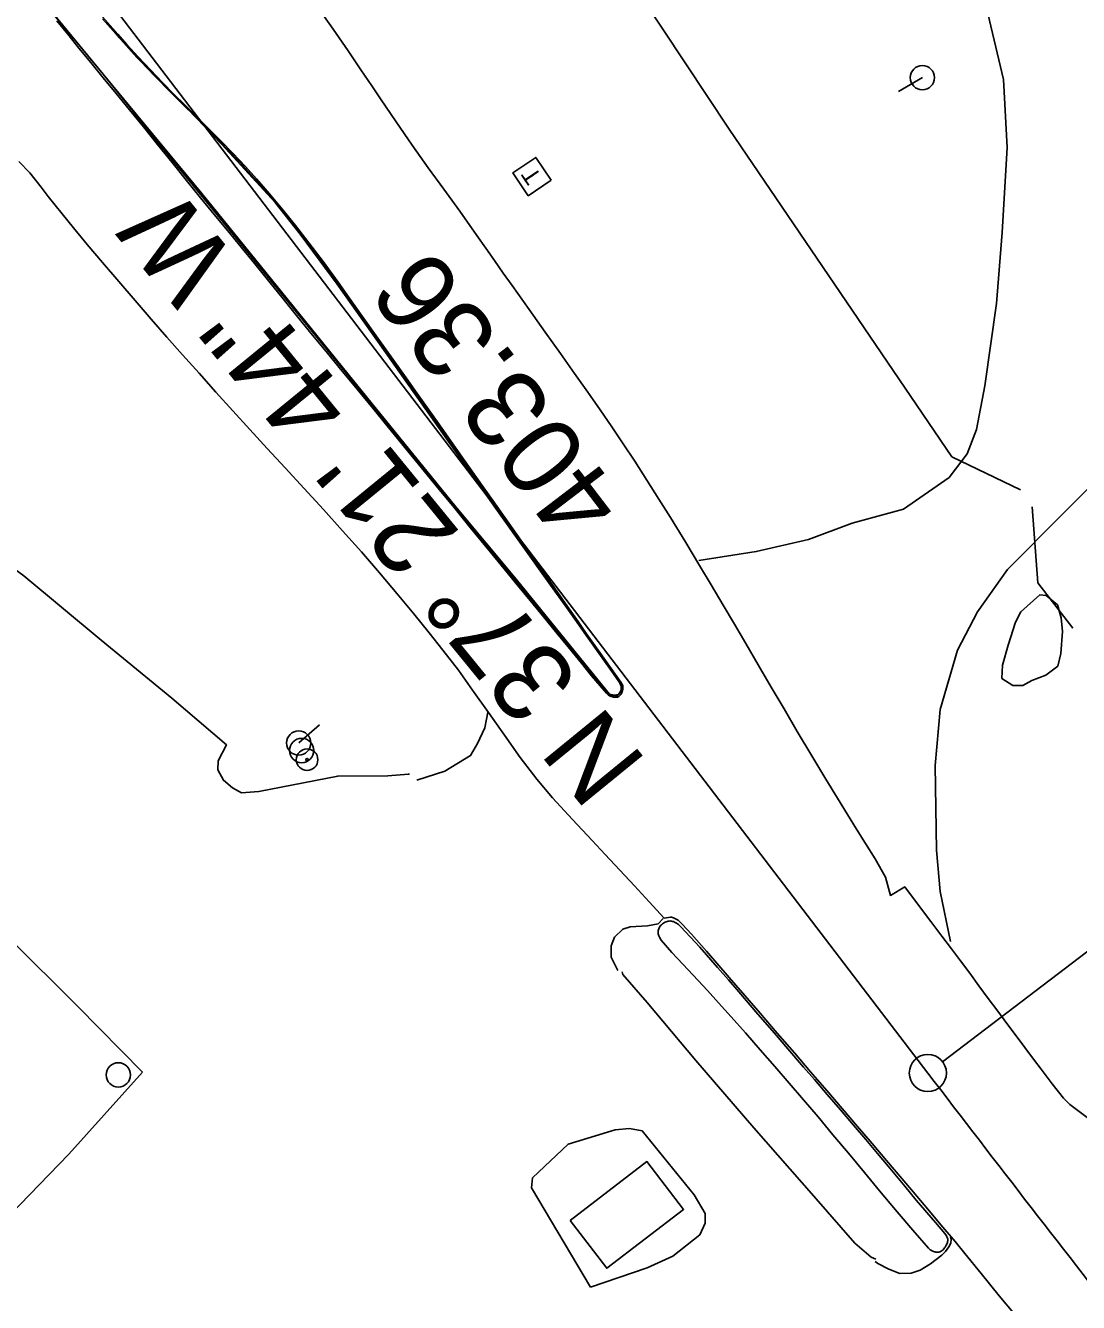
# Model space of a CAD drawing. Extents: x 471894 to 476235, y 503501 to 507878.
# Drawn here: x 473726.4 to 473939.4, y 505870.1 to 506128.6 of the extents above; entities that cross this region are included whole.
import ezdxf

# ---------------------------------------------------------------- set-up
doc = ezdxf.new("R2010")
doc.units = 0
for name, color, linetype in [('Exist Horizontal Alignment', 7, 'Continuous'), ('Exist Horizontal Alignment Direction Label', 7, 'Continuous'), ('Exist Other Culture Area Outline', 7, 'Continuous'), ('Exist Other Culture Fence Line', 7, 'Continuous'), ('Exist Other Culture Gate', 7, 'Continuous'), ('Exist Roads Curbs', 7, 'Continuous'), ('Exist Roads EOP', 7, 'Continuous'), ('Exist Roads EOP Other', 7, 'Continuous'), ('Exist Roads Soil', 7, 'Continuous'), ('Exist Utilities Other Located Object CELL', 7, 'Continuous'), ('Exist Utilities Other Pole CELL', 7, 'Continuous'), ('Exist Utilities Power Pole CELL', 7, 'Continuous'), ('Exist Utilities Telephone Pedestal CELL', 7, 'Continuous')]:
    doc.layers.add(name, color=color, linetype=linetype)

msp = doc.modelspace()

# ---------------------------------------------------------------- linework, layer by layer
at = {"layer": 'Exist Horizontal Alignment'}
for p, q in [((473908.93, 505916.58), (473664.15, 506237.18)), ((473911.91, 505918.85), (473979.21, 505970.23))]:
    msp.add_line(p, q, dxfattribs=at)
msp.add_circle((473908.93, 505916.58), 3.75, dxfattribs=at)
msp.add_arc((478558.54, 509466.62), 5849.93, 217.36226, 218.70549, dxfattribs=at)
at = {"layer": 'Exist Other Culture Area Outline'}
msp.add_lwpolyline([(473932.83, 506013.22), (473935.18, 506011.29), (473935.91, 506008.66), (473936.14, 506005.96), (473935.8, 506001.47), (473935.23, 505998.93), (473932.8, 505997.07), (473929.94, 505995.99), (473928.15, 505995.03), (473926.14, 505994.97), (473923.9, 505996.42), (473924.01, 505999.13), (473925.14, 506003.16), (473926.63, 506007.82), (473927.73, 506009.9), (473931.57, 506013.33), (473932.83, 506013.22)], dxfattribs=at)
msp.add_lwpolyline([(473836.55, 505886.76), (473852.1, 505898.67), (473859.52, 505888.98), (473843.98, 505877.07)], close=True, dxfattribs=at)
at = {"layer": 'Exist Other Culture Fence Line'}
msp.add_line((473938.23, 506006.61), (473931.19, 506015.78), dxfattribs=at)
msp.add_lwpolyline([(473913.78, 506041.26), (473868.72, 506107.56), (473819.7, 506181.61), (473863.62, 506226.96), (473925.15, 506291.5), (473965.74, 506322.98)], dxfattribs=at)
at = {"layer": 'Exist Other Culture Gate'}
for p, q in [((473927.69, 506034.58), (473913.78, 506041.26)), ((473931.19, 506015.78), (473930.02, 506031.17))]:
    msp.add_line(p, q, dxfattribs=at)
at = {"layer": 'Exist Roads Curbs'}
for points in [[(473729.8, 506133.75), (473747.2, 506112.55), (473762.04, 506094.58), (473779.35, 506073.27), (473791.58, 506058.07), (473813.37, 506031.23), (473825.63, 506016.54), (473837.49, 506001.85), (473844.51, 505993.27), (473845.56, 505993.02), (473846.36, 505993.17), (473846.82, 505993.81), (473846.92, 505994.37), (473846.89, 505994.89), (473846.65, 505995.44), (473846.47, 505995.98), (473832.29, 506015.75), (473821.57, 506030.85), (473810.83, 506045.98), (473797.68, 506064.6), (473789.47, 506076.22), (473781.98, 506086.36), (473776.89, 506092.71), (473766.1, 506104.47), (473757.5, 506113.42), (473748.94, 506122.09), (473741.98, 506129.92)], [(473731.9, 506131.08), (473742.1, 506118.69), (473753.47, 506104.63), (473767.01, 506088.03), (473778.28, 506074.2), (473790.38, 506059.26), (473804.31, 506042.24), (473817.69, 506025.78), (473833.87, 506005.97), (473842.71, 505995.12), (473844.02, 505993.55), (473844.49, 505993.19), (473844.75, 505993.04), (473845.13, 505992.95), (473845.54, 505992.9), (473845.93, 505992.93), (473846.26, 505993.13), (473846.52, 505993.37), (473846.65, 505993.59), (473846.79, 505993.85), (473846.87, 505994.08), (473846.91, 505994.35), (473846.92, 505994.6), (473846.91, 505994.86), (473846.7, 505995.43), (473846.3, 505996.03), (473844.17, 505999.01), (473840.22, 506004.61), (473832.1, 506016.1), (473826.41, 506024.14), (473818.83, 506034.91), (473810.76, 506046.32), (473804, 506055.98), (473797.9, 506064.54), (473790.82, 506074.63), (473788.67, 506077.63), (473786.81, 506080.13), (473784.08, 506083.78), (473782.07, 506086.35), (473779.85, 506089.26), (473777.62, 506091.92), (473775.42, 506094.52), (473773.65, 506096.53), (473771.95, 506098.47), (473769.74, 506100.89), (473767.48, 506103.28), (473764.28, 506106.6), (473760.94, 506109.91), (473758.03, 506112.78), (473755.47, 506115.31), (473752.82, 506118.01), (473750.81, 506120.14), (473748.4, 506122.79), (473745.45, 506126.08), (473742.7, 506129.22)]]:
    msp.add_lwpolyline(points, dxfattribs=at)
msp.add_lwpolyline([(473902.72, 505888.5), (473905.88, 505884.75), (473909.07, 505881.14), (473909.41, 505880.82), (473910.07, 505880.48), (473910.24, 505880.41), (473910.41, 505880.36), (473910.56, 505880.32), (473910.71, 505880.3), (473910.86, 505880.3), (473911.01, 505880.3), (473911.16, 505880.33), (473911.32, 505880.37), (473911.48, 505880.43), (473911.65, 505880.53), (473911.82, 505880.65), (473912, 505880.81), (473912.32, 505881.17), (473912.45, 505881.35), (473912.66, 505881.73), (473912.82, 505882.1), (473912.88, 505882.29), (473912.92, 505882.47), (473912.95, 505882.64), (473912.95, 505882.79), (473912.94, 505882.93), (473912.88, 505883.19), (473912.79, 505883.46), (473912.71, 505883.63), (473912.37, 505884.11), (473910.5, 505886.33), (473906.58, 505890.88), (473904.3, 505893.65), (473900.92, 505897.72), (473898.75, 505900.31), (473896.38, 505903.13), (473893.89, 505906.06), (473891.28, 505909.11), (473888.56, 505912.26), (473885.99, 505915.25), (473883.8, 505917.78), (473880.62, 505921.47), (473877.91, 505924.62), (473874.57, 505928.51), (473870.7, 505933), (473868.6, 505935.42), (473866.4, 505937.94), (473862.83, 505942.02), (473858.96, 505946.18), (473858.47, 505946.62), (473858.06, 505946.91), (473857.67, 505947.13), (473857.48, 505947.21), (473857.29, 505947.27), (473857.1, 505947.31), (473856.92, 505947.34), (473856.74, 505947.35), (473856.55, 505947.34), (473856.37, 505947.31), (473856.18, 505947.26), (473856, 505947.2), (473855.81, 505947.12), (473855.63, 505947.02), (473855.28, 505946.79), (473855.02, 505946.59), (473854.94, 505946.5), (473854.79, 505946.31), (473854.64, 505946.08), (473854.57, 505945.94), (473854.5, 505945.78), (473854.39, 505945.41), (473854.36, 505945.2), (473854.35, 505944.99), (473854.38, 505944.77), (473854.43, 505944.54), (473854.51, 505944.31), (473854.63, 505944.05), (473854.98, 505943.48), (473857.16, 505940.96), (473859.37, 505938.6), (473862.46, 505935.32), (473864.38, 505933.26), (473866.61, 505930.81), (473869.16, 505927.96), (473872.01, 505924.72), (473875.01, 505921.29), (473877.97, 505917.88), (473880.89, 505914.5), (473883.78, 505911.13), (473886.71, 505907.7), (473889.73, 505904.1), (473892.87, 505900.36), (473896.1, 505896.46), (473899.18, 505892.74)], close=True, dxfattribs=at)
at = {"layer": 'Exist Roads EOP'}
for points in [[(473732.76, 506129.5), (473734.94, 506126.82), (473737.22, 506124), (473739.62, 506121.06), (473742.14, 506117.98), (473744.76, 506114.78), (473747.47, 506111.46), (473750.26, 506108.03), (473753.12, 506104.49), (473756.05, 506100.85), (473758.98, 506097.21), (473761.83, 506093.69), (473764.6, 506090.28), (473767.3, 506086.99), (473770, 506083.71), (473772.77, 506080.32), (473775.62, 506076.82), (473778.54, 506073.22), (473781.51, 506069.56), (473784.49, 506065.92), (473787.47, 506062.28), (473790.46, 506058.64), (473793.5, 506054.95), (473796.63, 506051.14), (473799.85, 506047.21), (473803.16, 506043.16), (473806.51, 506039.07), (473809.82, 506035.01), (473813.1, 506030.99), (473816.34, 506027), (473819.52, 506023.1), (473822.6, 506019.33), (473825.58, 506015.69), (473828.46, 506012.19), (473831.23, 506008.83), (473833.89, 506005.6), (473836.42, 506002.5), (473838.84, 505999.53), (473840.92, 505996.98), (473843.9, 505993.42), (473844.23, 505993.13), (473844.55, 505992.93), (473844.84, 505992.78), (473845.11, 505992.69), (473845.37, 505992.63), (473845.64, 505992.6), (473845.9, 505992.61), (473846.15, 505992.67), (473846.39, 505992.79), (473846.63, 505992.98), (473846.85, 505993.2), (473846.99, 505993.44), (473847.1, 505993.68), (473847.18, 505993.93), (473847.24, 505994.18), (473847.26, 505994.44), (473847.25, 505994.7), (473847.2, 505994.97), (473847.13, 505995.14), (473846.82, 505995.65), (473844.84, 505998.46), (473842.25, 506002.13), (473839.57, 506005.93), (473838.18, 506007.92), (473836.03, 506010.97), (473832.44, 506016.08), (473829.92, 506019.66), (473827.4, 506023.23), (473824.16, 506027.84), (473820.92, 506032.44), (473817.66, 506037.06), (473814.41, 506041.67), (473811.87, 506045.28), (473809.32, 506048.88), (473805.65, 506054.07), (473803.4, 506057.25), (473800.34, 506061.53), (473797.36, 506065.73), (473794.52, 506069.73), (473791.9, 506073.47), (473789.66, 506076.63), (473786.61, 506080.82), (473783.74, 506084.6), (473781.02, 506088.11), (473778.46, 506091.27), (473775.73, 506094.52), (473773.13, 506097.53), (473770.91, 506100.04), (473768.29, 506102.82), (473765.98, 506105.18), (473763.36, 506107.81), (473760.92, 506110.23), (473758.62, 506112.49), (473756.43, 506114.67), (473754.18, 506116.97), (473751.7, 506119.58), (473749.22, 506122.25), (473746.93, 506124.73), (473745.07, 506126.78), (473741.54, 506130.87)], [(473785.56, 506132.21), (473788.61, 506127.81), (473791.64, 506123.42), (473794.26, 506119.61), (473796.46, 506116.38), (473798.24, 506113.74), (473801.41, 506109.05), (473804.63, 506104.36), (473807.85, 506099.79), (473811.01, 506095.43), (473814.25, 506090.96), (473817.71, 506086.07), (473819.5, 506083.53), (473821.27, 506080.99), (473823.05, 506078.47), (473824.83, 506075.95), (473828.28, 506071.06), (473831.54, 506066.48), (473834.6, 506062.18), (473837.46, 506058.14), (473840.14, 506054.36), (473842.63, 506050.79), (473845.01, 506047.35), (473847.32, 506043.91), (473849.65, 506040.37), (473852.1, 506036.58), (473854.54, 506032.73), (473856.89, 506028.99), (473859.99, 506023.94), (473862.75, 506019.3), (473865.08, 506015.39), (473867.53, 506011.27), (473869.8, 506007.44), (473872.09, 506003.53), (473874.62, 505999.19), (473877.25, 505994.68), (473879.84, 505990.26), (473882.52, 505985.71), (473885.45, 505980.77), (473888.27, 505976.06), (473890.62, 505972.19), (473892.65, 505968.89), (473894.5, 505965.92), (473896.32, 505963), (473898.25, 505959.9), (473900.39, 505956.24), (473901.35, 505952.53), (473904.26, 505954.24), (473907.02, 505950.56), (473909.51, 505947.25), (473911.74, 505944.29), (473913.7, 505941.7), (473915.53, 505939.26), (473917.39, 505936.78), (473919.26, 505934.25), (473921.15, 505931.68), (473923.05, 505929.1), (473924.92, 505926.57), (473926.78, 505924.08), (473930.33, 505919.35), (473931.82, 505917.39), (473934.09, 505914.38), (473936.35, 505911.48), (473937.65, 505910.24), (473941.72, 505907.16)], [(473926.5, 505867.73), (473923.38, 505871.52), (473919.69, 505876.03), (473916.39, 505880.07), (473914.42, 505882.46), (473911.58, 505885.89), (473909.26, 505888.63), (473905.59, 505892.95), (473900.56, 505898.86), (473897.63, 505902.31), (473894.69, 505905.75), (473891.59, 505909.38), (473888.48, 505913.01), (473885.2, 505916.83), (473881.92, 505920.65), (473878.47, 505924.65), (473875.02, 505928.66), (473871.89, 505932.28), (473868.76, 505935.9), (473864.14, 505941.24), (473861.14, 505944.68), (473859.25, 505946.73), (473858.39, 505947.49), (473858.05, 505947.71), (473857.5, 505947.98), (473857.28, 505948.06), (473857.1, 505948.09), (473856.88, 505948.09), (473855.57, 505947.94), (473852.55, 505951.22), (473849.56, 505954.45), (473846.6, 505957.63), (473843.68, 505960.77), (473841, 505963.62), (473837.05, 505967.86), (473833.03, 505972.25), (473829.83, 505976.03), (473826.49, 505980.44), (473823.28, 505984.98), (473820.08, 505989.55), (473816.84, 505994.08), (473813.96, 505998.08), (473810.85, 506002.15), (473808.07, 506005.65), (473804.95, 506009.49), (473801.58, 506013.57), (473798.03, 506017.77), (473794.35, 506022.04), (473790.55, 506026.32), (473786.67, 506030.61), (473782.75, 506034.88), (473778.91, 506039.03), (473775.29, 506042.96), (473771.79, 506046.78), (473768.34, 506050.59), (473764.92, 506054.39), (473761.52, 506058.19), (473758.19, 506061.91), (473755.01, 506065.5), (473751.85, 506069.11), (473748.58, 506072.9), (473745.27, 506076.76), (473742, 506080.59), (473738.9, 506084.26), (473736.09, 506087.63), (473733.8, 506090.42), (473731.01, 506093.94), (473729.57, 506095.83), (473727.25, 506098.75), (473725.07, 506101.03)]]:
    msp.add_lwpolyline(points, dxfattribs=at)
at = {"layer": 'Exist Roads EOP Other'}
for points in [[(473913.27, 506037.11), (473916.89, 506041.85), (473918.75, 506046.79), (473920.43, 506055.64), (473922.84, 506072.28), (473923.93, 506086.64), (473924.98, 506103.87), (473924.26, 506117.61), (473920.13, 506135.01)], [(473913.51, 505943.17), (473911.45, 505953.3), (473910.68, 505961.68), (473910.41, 505978.78), (473911.43, 505990.12), (473914.92, 506002.14), (473918.98, 506009.94), (473925.07, 506018.5), (473936, 506029.52), (473947.63, 506041.17), (473965.19, 506055.46), (473982.69, 506070.41), (473990.83, 506076.86), (474006.86, 506094.18), (474011.93, 506100.52), (474025.84, 506111.79), (474039.24, 506123), (474044.06, 506126.93)], [(473804.1, 505977.12), (473803.9, 505977.06), (473799.7, 505976.69), (473789.56, 505976.67), (473778.14, 505974.45), (473773.59, 505973.52), (473770.1, 505973.29), (473768.28, 505974.3), (473766.48, 505975.83), (473765.34, 505977.91), (473765.4, 505979.74), (473767.08, 505982.97), (473755.99, 505992.41), (473741.7, 506004.2), (473726.1, 506017.21), (473707.96, 506030.39), (473685.74, 506050.29), (473682.56, 506052.7), (473675.11, 506045.13), (473669.11, 506039.17), (473665.82, 506036.28)], [(473862.59, 506020.28), (473874.2, 506022.11), (473884.81, 506024.57), (473893.59, 506027.83), (473904, 506030.71), (473913.27, 506037.11)], [(473623.17, 505862.54), (473631.67, 505871.55), (473635.86, 505873.86), (473659.81, 505895.65), (473701.95, 505932.97), (473710.11, 505940.82), (473713.9, 505943.62), (473716.67, 505945.1), (473720.03, 505945.14), (473723.01, 505943.95), (473737.02, 505930.05), (473750.05, 505916.76)], [(473685.49, 505848.83), (473735.17, 505900.17), (473750.05, 505916.76)], [(473836.15, 505902.2), (473845.66, 505905.08), (473848.56, 505905.38), (473851.17, 505904.86), (473861.66, 505891.91), (473863.88, 505888.16), (473863.88, 505886.17), (473862.8, 505883.81), (473857.37, 505879.49), (473852.15, 505877.15), (473840.7, 505873.22)], [(473840.7, 505873.22), (473828.75, 505893.36), (473828.97, 505895.35), (473836.15, 505902.2)]]:
    msp.add_lwpolyline(points, dxfattribs=at)
at = {"layer": 'Exist Roads Soil'}
for points in [[(473819.95, 505989.58), (473819.32, 505986.4), (473817.86, 505983.25), (473816.45, 505980.81), (473811.23, 505977.65), (473805.55, 505975.86)], [(473846.23, 505937.34), (473844.9, 505940), (473844.87, 505942.34), (473845.57, 505944.07), (473847.24, 505945.71), (473848.73, 505946.18), (473852.25, 505946.39), (473854.37, 505946.76), (473855.37, 505947.83)], [(473898.43, 505878.88), (473897.43, 505879.33), (473894.18, 505882.14), (473885.84, 505891.65), (473873.72, 505905.48), (473862.02, 505919.12), (473852.14, 505930.86), (473847.26, 505936.54), (473847.09, 505937.05)], [(473913.5, 505883.46), (473913.62, 505882.93), (473913.58, 505882.14), (473913.19, 505881.4), (473912.47, 505880.43), (473911.76, 505879.71), (473909.48, 505877.95), (473907.38, 505876.66), (473905.54, 505876.06), (473903.29, 505875.98), (473901.02, 505876.9), (473898.8, 505878.06), (473898.25, 505878.45)]]:
    msp.add_lwpolyline(points, dxfattribs=at)
at = {"layer": 'Exist Utilities Other Located Object CELL'}
for radius in [2.18, 0.24]:
    msp.add_circle((473783.36, 505979.99), radius, dxfattribs=at)
at = {"layer": 'Exist Utilities Other Pole CELL'}
for centre in [(473782.26, 505981.84), (473745.19, 505916.2)]:
    msp.add_circle(centre, 2.46, dxfattribs=at)
at = {"layer": 'Exist Utilities Power Pole CELL'}
for p, q in [((473907.83, 506118.01), (473902.97, 506115.18)), ((473907.83, 506118.01), (473907.83, 506118.01)), ((473781.67, 505983.37), (473785.9, 505987.07)), ((473781.67, 505983.37), (473781.67, 505983.37))]:
    msp.add_line(p, q, dxfattribs=at)
for centre in [(473907.83, 506118.01), (473781.67, 505983.37)]:
    msp.add_circle(centre, 2.45, dxfattribs=at)
at = {"layer": 'Exist Utilities Telephone Pedestal CELL'}
msp.add_line((473828.88, 506097.92), (473828.88, 506097.92), dxfattribs=at)
msp.add_lwpolyline([(473832.75, 506097.23), (473829.63, 506101.88), (473824.98, 506098.75), (473828.11, 506094.11), (473832.75, 506097.23)], dxfattribs=at)

# ---------------------------------------------------------------- texts
at = {"layer": 'Exist Horizontal Alignment Direction Label'}
for s, rotation, p in [('N 37%%d 21\' 44" W', 129.2263, (473852.36, 505979.47)), ('403.36', 127.3623, (473848.02, 506032.07))]:
    msp.add_text(s, height=16, rotation=rotation, dxfattribs=at).set_placement(p)
at = {"layer": 'Exist Utilities Telephone Pedestal CELL'}
msp.add_text('T', height=3.42, rotation=123.9249, dxfattribs=at).set_placement((473830.94, 506097.93))

doc.saveas('drawing.dxf')
